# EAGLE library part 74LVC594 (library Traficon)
8-bit SHIFT REGISTER, output latch
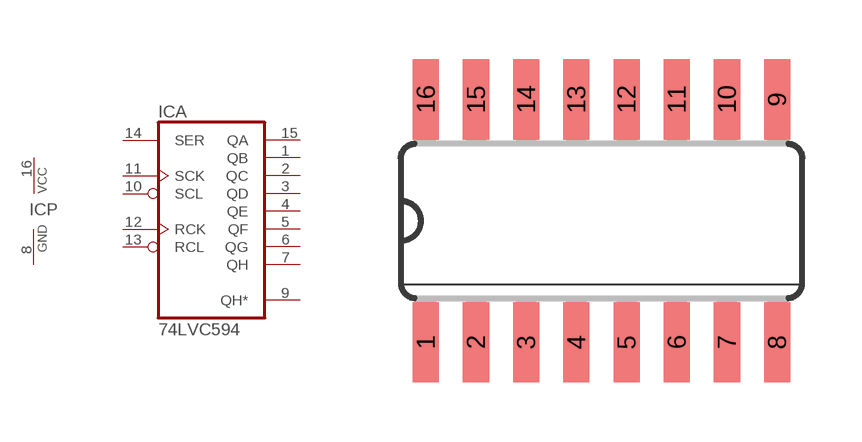
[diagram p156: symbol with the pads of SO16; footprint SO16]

Designator prefix IC; gates A=74594 P=PWRN-3

## 74LVC594HCD, 74LVC594HCTD, 74LVC594LSD  [SO16]
1  A:QB  out
2  A:QC  out
3  A:QD  out
4  A:QE  out
5  A:QF  out
6  A:QG  out
7  A:QH  out
8  P:GND  pwr
9  A:QH*  out
10  A:SCL  in
11  A:SCK  in
12  A:RCK  in
13  A:RCL  in
14  A:SER  in
15  A:QA  out
16  P:VCC  pwr

## Footprint SO16 (pad centres in mm)
Small Outline package 150 mil
smd 0.66 x 2.032: 1 -4.445,-3.073; 2 -3.175,-3.073; 3 -1.905,-3.073; 4 -0.635,-3.073; 5 0.635,-3.073; 6 1.905,-3.073; 7 3.175,-3.073; 8 4.445,-3.073; 9 4.445,3.073; 10 3.175,3.073; 11 1.905,3.073; 12 0.635,3.073; 13 -0.635,3.073; 14 -1.905,3.073; 15 -3.175,3.073; 16 -4.445,3.073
